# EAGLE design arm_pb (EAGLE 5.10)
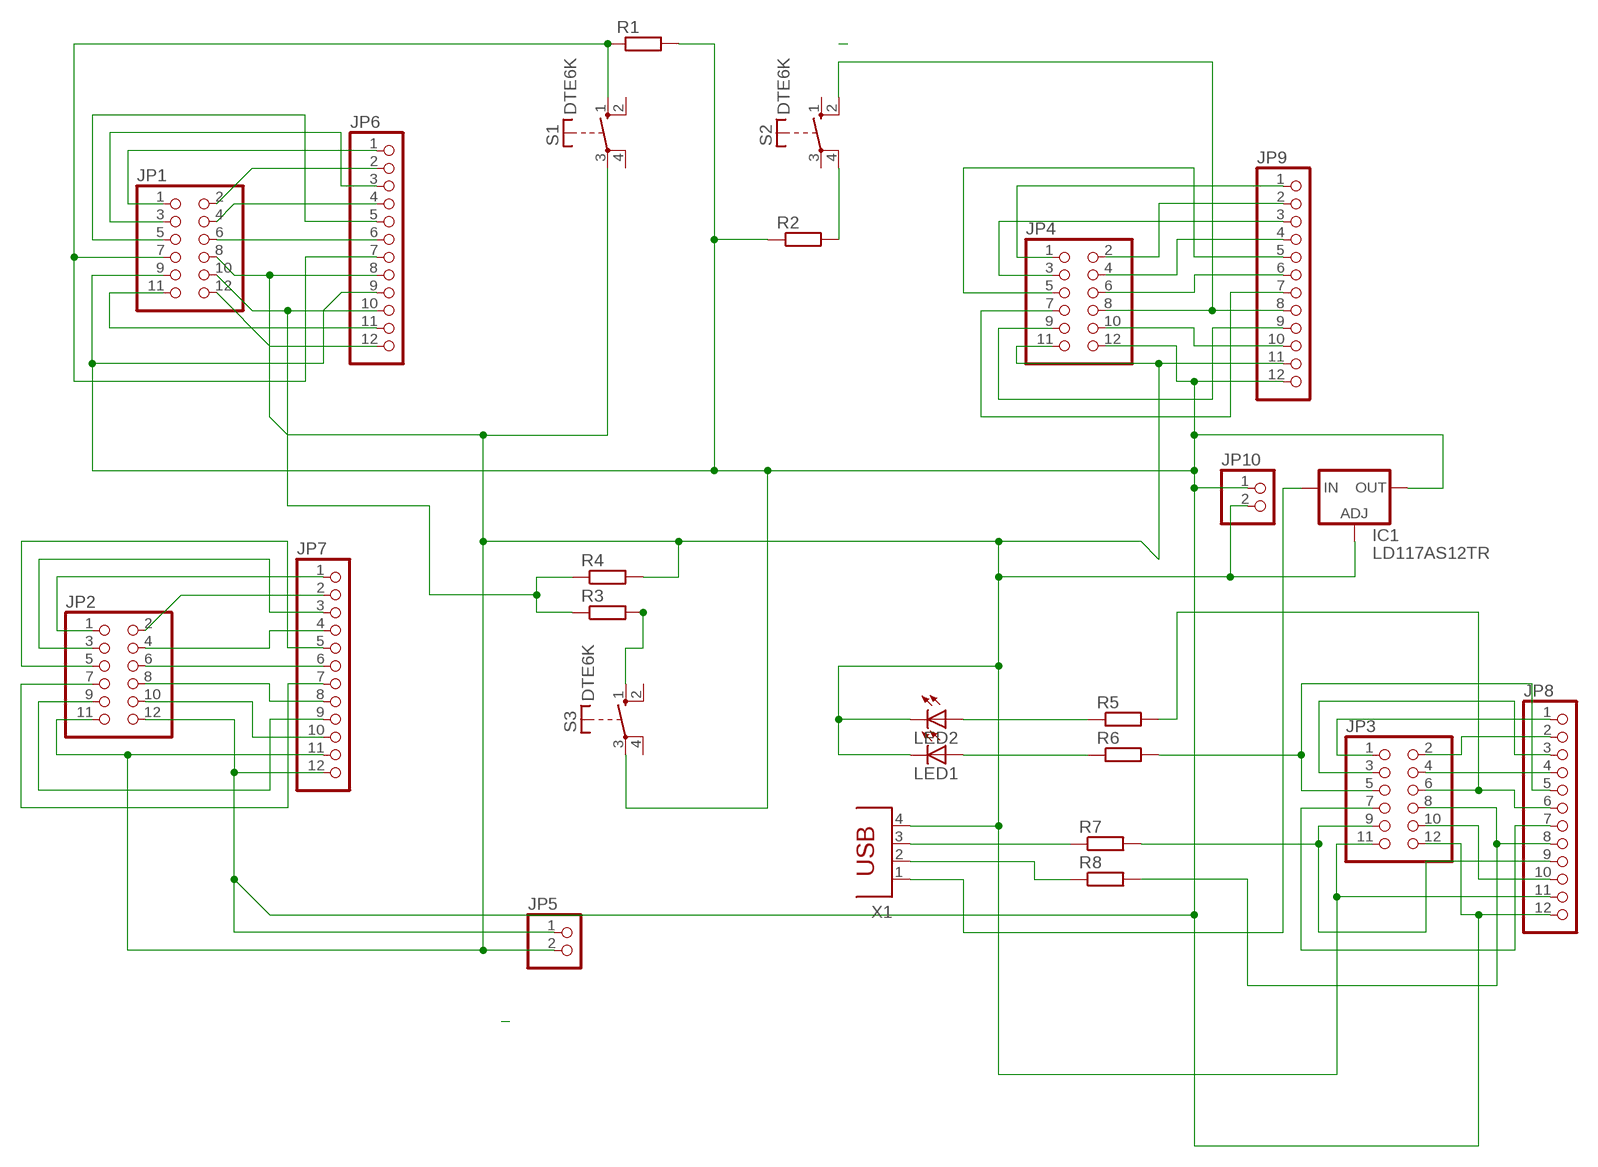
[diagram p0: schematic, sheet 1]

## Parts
IC1  LD117AS12TR  [SOT223]
JP1  PINHD-2X6  [2X06]
JP2  PINHD-2X6  [2X06]
JP3  PINHD-2X6  [2X06]
JP4  PINHD-2X6  [2X06]
JP5  PINHD-1X2  [1X02]
JP6  PINHD-1X12  [1X12]
JP7  PINHD-1X12  [1X12]
JP8  PINHD-1X12  [1X12]
JP9  PINHD-1X12  [1X12]
JP10  PINHD-1X2  [1X02]
LED1  LED3MM  [LED3MM]
LED2  LED3MM  [LED3MM]
R1  R-EU_0204/7  [0204/7]
R2  R-EU_0204/7  [0204/7]
R3  R-EU_0204/7  [0204/7]
R4  R-EU_0204/7  [0204/7]
R5  R-EU_0204/7  [0204/7]
R6  R-EU_0204/7  [0204/7]
R7  R-EU_0204/7  [0204/7]
R8  R-EU_0204/7  [0204/7]
S1  DTE6K  [DTE6K]
S2  DTE6K  [DTE6K]
S3  DTE6K  [DTE6K]
X1  PN61729  [PN61729]

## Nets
N$1: JP1.2 JP6.2
N$3: JP1.4 JP6.4
N$4: JP1.6 JP6.6
N$6: JP1.12 JP6.12
N$7: JP1.10 JP6.10 R3.1 R4.1
N$8: JP1.11 JP6.11
N$10: JP1.7 JP6.7 R1.1 S1.1(S)
N$11: JP1.1 JP6.1
N$12: JP1.3 JP6.3
N$13: JP1.5 JP6.5
N$14: JP3.2 JP8.2
N$15: JP3.4 JP8.4
N$16: JP3.6 JP8.6 R5.2
N$17: JP3.8 JP8.8 R8.2
N$18: JP3.10 JP8.10
N$19: IC1.3(IN) X1.1
N$21: JP3.9 JP8.9 R7.2
N$22: R2.2 S2.4(P)
N$23: R7.1 X1.3
N$24: JP3.1 JP8.1
N$25: JP3.3 JP8.3
N$26: JP3.7 JP8.7
N$27: JP3.5 JP8.5 R6.2
N$28: JP2.2 JP7.2
N$29: JP2.4 JP7.4
N$30: JP2.6 JP7.6
N$31: JP2.8 JP7.8
N$32: JP2.10 JP7.10
N$34: R8.1 X1.2
N$35: JP2.9 JP7.9
N$36: JP2.7 JP7.7
N$37: JP2.1 JP7.1
N$38: JP2.3 JP7.3
N$39: JP2.5 JP7.5
N$41: JP4.2 JP9.2
N$42: JP4.4 JP9.4
N$48: JP4.6 JP9.6
N$50: JP4.8 JP9.8 S2.2(S)
N$53: JP4.10 JP9.10
N$54: LED2.A R5.1
N$55: LED1.A R6.1
N$57: JP4.7 JP9.7
N$58: JP4.1 JP9.1
N$59: JP4.3 JP9.3
N$60: JP4.5 JP9.5
N$61: JP4.9 JP9.9
N$136: R3.2 S3.1(S)
N$179: IC1.1(ADJ) JP1.8 JP2.11 JP3.11 JP4.11 JP5.2 JP6.8 JP7.11 JP8.11 JP9.11 JP10.2 LED1.K(C) LED2.K(C) R4.2 S1.3(P) X1.4
N$183: IC1.4(OUT) JP1.9 JP2.12 JP3.12 JP4.12 JP5.1 JP6.9 JP7.12 JP8.12 JP9.12 JP10.1 R1.2 R2.1 S3.3(P)
Unconnected: S1.2(S) S1.4(P) S2.1(S) S2.3(P) S3.2(S) S3.4(P)

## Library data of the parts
IC1 = v-reg:LD117A?*: Low drop fixed and adjustable positive voltage regulators 1 A Source: http://www.st.com/stonline/products/literature/ds/7194/ld1117axx.pdf
JP1-JP4 = pinhead:PINHD-2X6: PIN HEADER
JP5 JP10 = pinhead:PINHD-1X2: PIN HEADER
JP6-JP9 = pinhead:PINHD-1X12: PIN HEADER
LED1 LED2 = led:LED: LED
R1-R8 = rcl:R-EU_: RESISTOR, European symbol
S1-S3 = switch-misc:DT: ITT SWITCH
X1 = con-berg:PN61729: BERG USB connector

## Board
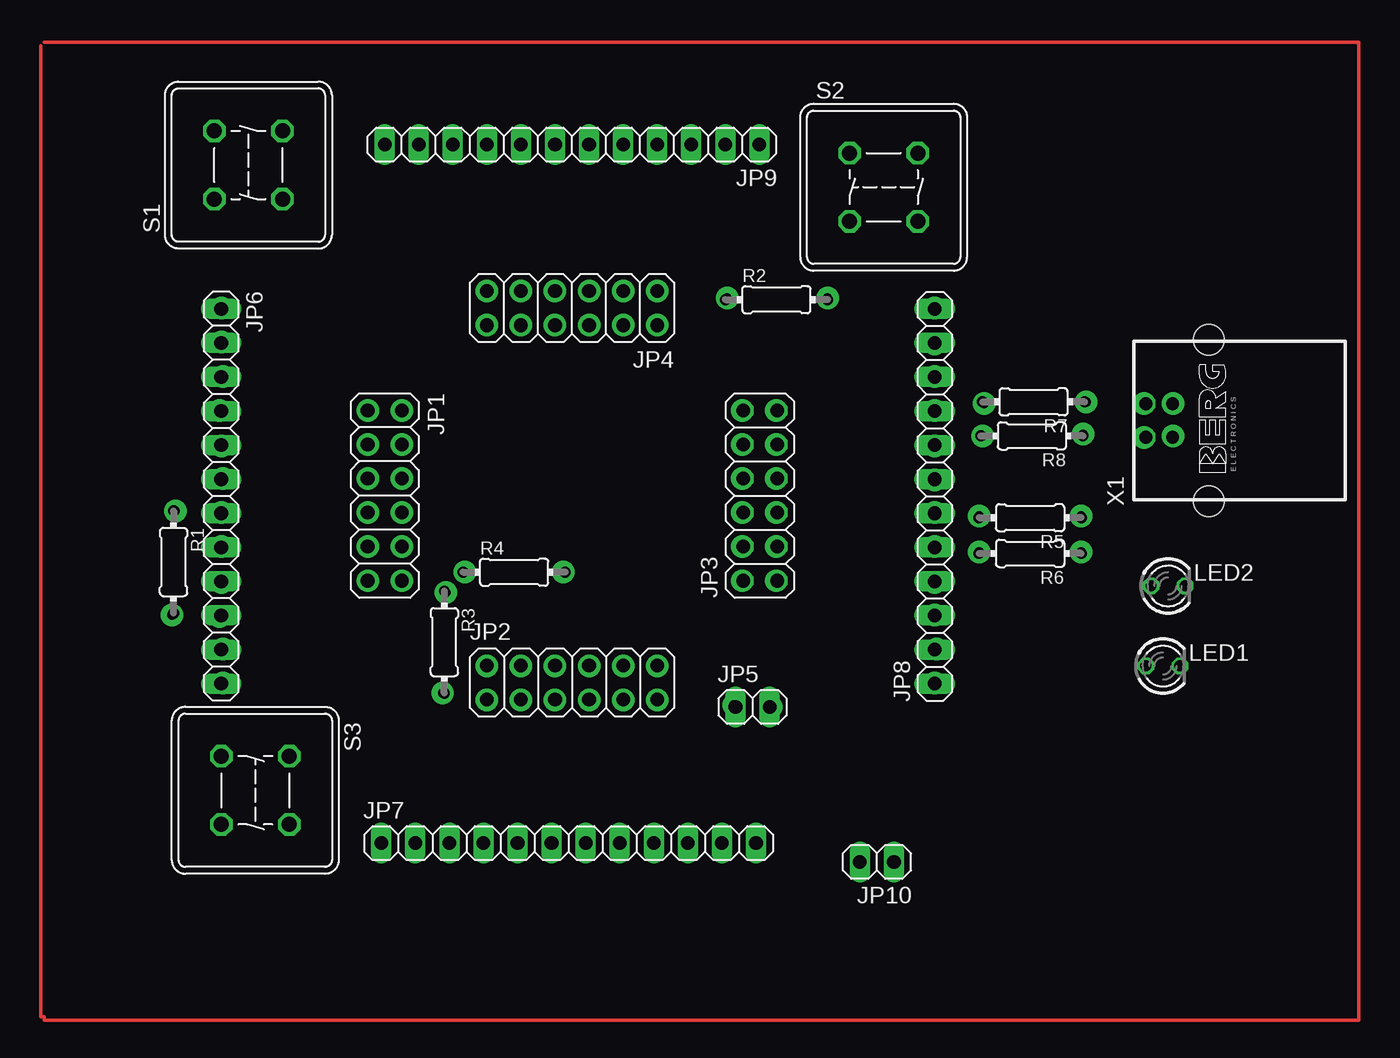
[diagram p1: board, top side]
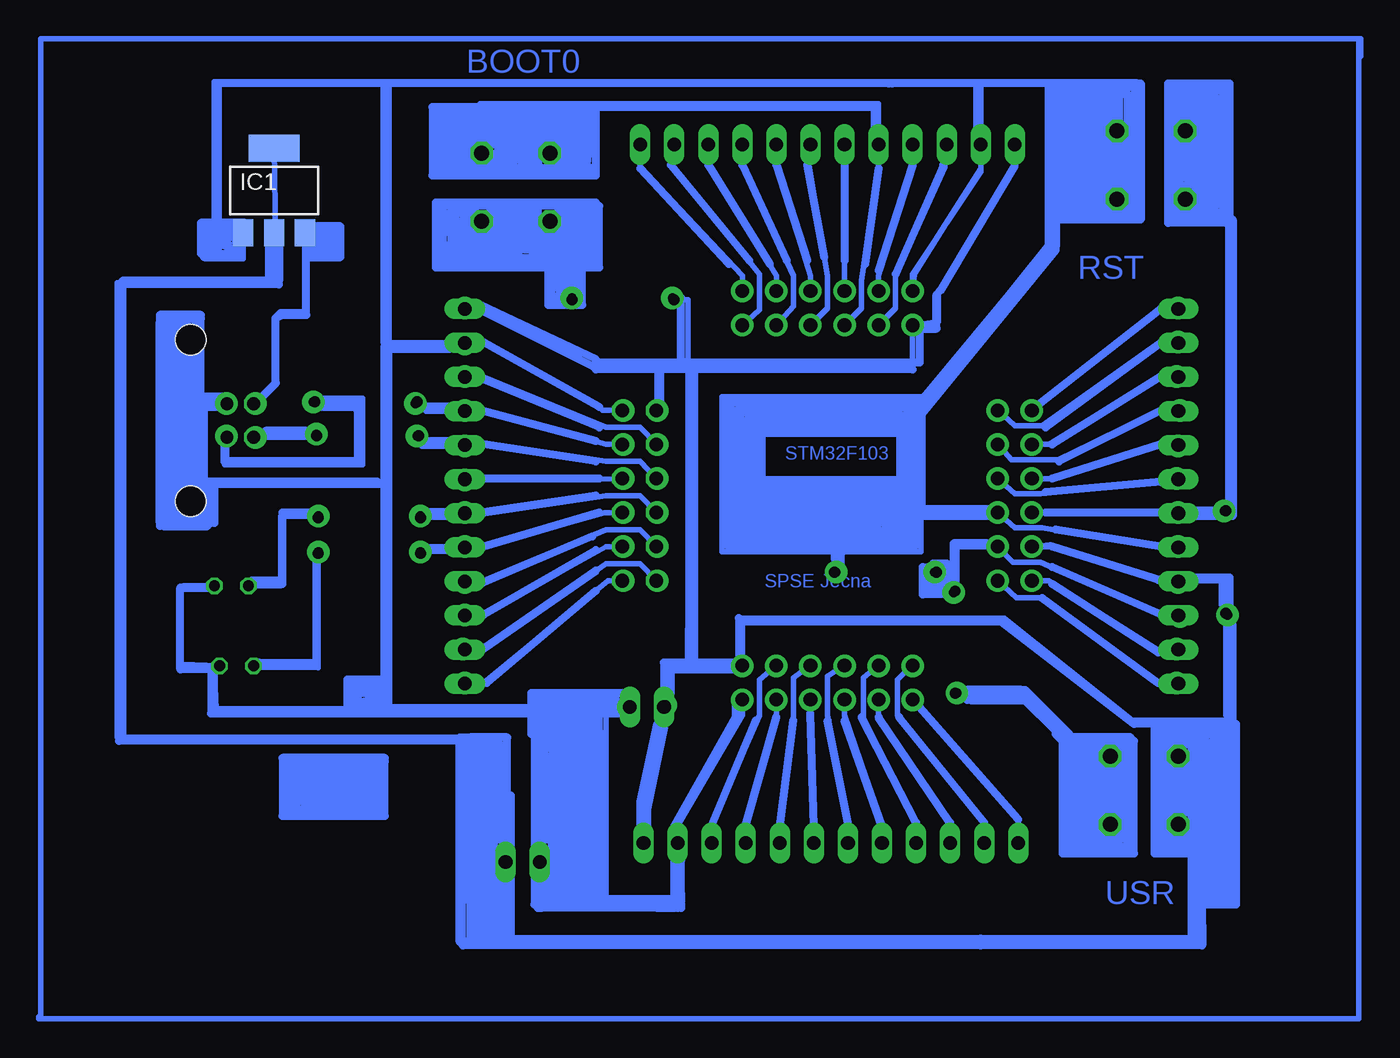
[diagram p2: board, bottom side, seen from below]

No outline drawn. Coordinates in mm, seen from the top.
Copper layers (1*16): Top 0.035mm / dielectric 1.5mm / Bottom 0.035mm
Design rules: minimum track width 0.2mm, minimum drill 0.6mm, track to track 0.2mm, track to pad 0.2mm, pad to pad 0.2mm, via to via 0.2mm, smd to smd 8mil, copper to edge 40mil, drill to drill 2mm, minimum pad ring 0.2mm, minimum via ring 0.3mm, stop-mask expansion 4mil, vias tented up to drill 0mil, thermal gap 10mil

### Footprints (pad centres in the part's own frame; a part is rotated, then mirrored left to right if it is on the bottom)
SOT223 = smd 1.5 x 2: 1 -2.3,-3.15; 2 0,-3.15; 3 2.3,-3.15 | smd 3.8 x 2: 4 0,3.15
2X06 = drill 1.016 octagon: 1 -6.35,-1.27; 2 -6.35,1.27; 3 -3.81,-1.27; 4 -3.81,1.27; 5 -1.27,-1.27; 6 -1.27,1.27; 7 1.27,-1.27; 8 1.27,1.27; 9 3.81,-1.27; 10 3.81,1.27; 11 6.35,-1.27; 12 6.35,1.27
1X02 = drill 1.016 long: 1 -1.27,0; 2 1.27,0
1X12 = drill 1.016 long: 1 -13.97,0; 2 -11.43,0; 3 -8.89,0; 4 -6.35,0; 5 -3.81,0; 6 -1.27,0; 7 1.27,0; 8 3.81,0; 9 6.35,0; 10 8.89,0; 11 11.43,0; 12 13.97,0
LED3MM = drill 0.813 octagon: A -1.27,0; K 1.27,0
0204/7 = drill 0.813 octagon: 1 -3.81,0; 2 3.81,0
DTE6K = drill 1.118 octagon: 1 -2.54,2.54; 2 2.54,2.54; 3 2.54,-2.54; 4 -2.54,-2.54
PN61729 = drill 0.95 octagon: 1 1.25,4.71; 2 -1.25,4.71; 3 -1.25,2.71; 4 1.25,2.71 | hole 2.3: -6.02,0; 6.02,0

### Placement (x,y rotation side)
IC1  67.94,54.48 0 bottom
JP1  12.7,31.75 270 top
JP2  26.67,17.82 0 top
JP3  40.7,31.75 90 top
JP4  26.67,45.72 180 top
JP5  40.13,16 0 top
JP6  0.51,31.7 270 top
JP7  26.42,5.84 0 top
JP8  53.72,31.7 90 top
JP9  26.67,57.91 180 top
JP10  49.4,4.45 180 top
LED1  70.74,19.05 0 top
LED2  71.12,25.02 0 top
R1  -3.05,26.8 270 top
R2  41.91,46.35 0 top
R3  17.14,20.83 270 top
R4  22.35,26.04 0 top
R5  60.83,30.1 180 top
R6  60.83,27.43 180 top
R7  61.09,38.73 180 top
R8  60.96,36.2 180 top
S1  2.54,56.39 90 top
S2  49.91,54.74 0 top
S3  3.05,9.78 270 top
X1  74.17,37.34 90 top

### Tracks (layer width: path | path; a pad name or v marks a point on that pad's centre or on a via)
N$1
  Bottom 0.406: JP1.2 12.7,36.96 10.67,36.96 1.91,43.18 JP6.2
N$2
  Top 0.254: -12.7,65.53 85.34,65.53 85.34,-7.37 -12.7,-7.37 -12.7,-7.11 -12.95,-7.11 -12.95,65.28
N$3
  Bottom 0.406: JP1.4 12.95,34.42 9.53,34.42 1.91,38.1 JP6.4
N$4
  Bottom 0.406: JP1.6 12.7,31.88 10.79,31.88 JP6.6
N$5
  Bottom 0.406: 19.56,39.12 34.54,39.12 34.54,27.56 19.68,27.56 19.68,30.35 21.34,30.35 21.34,33.02 | 21.34,33.15 21.34,36.32 31.5,36.32 31.5,33.02 21.34,33.02 | 21.34,33.02 21.34,33.15 | 21.34,33.15 21.08,33.15 21.08,30.73 19.81,30.73 19.81,37.59 19.81,38.86 34.16,38.86 34.16,27.94 20.07,27.94 20.07,30.1 21.72,30.1 21.72,32.77 31.88,32.77 31.88,36.58 20.95,36.58 20.95,33.4 20.83,33.4 20.83,31.11 20.57,31.11 | 20.32,31.11 20.07,31.11 20.07,38.61 20.32,38.61 | 20.32,38.61 20.32,38.73 | 20.32,38.61 20.32,31.11 | 20.32,31.11 20.57,31.11 | 20.57,31.11 20.57,38.61 33.78,38.61 33.78,28.19 20.45,28.19 20.45,29.84 22.1,29.84 22.1,32.51 32.26,32.51 | 32.26,32.51 32.26,32.38 | 32.26,32.51 32.26,36.83 20.83,36.83 20.83,38.23 33.4,38.23 33.4,28.45 20.7,28.45 20.7,29.59 22.48,29.59 22.48,32.26 32.51,32.26 32.51,37.08 21.21,37.08 21.21,37.34 | 21.21,37.72 21.21,37.85 33.15,37.85 33.15,37.47 33.02,37.47 33.02,28.7 20.95,28.7 20.95,29.21 22.86,29.21 22.86,32 32.77,32 32.77,31.75 32.64,31.75 | 32.64,37.34 32.64,37.72 21.21,37.72 | 21.21,37.72 21.21,37.34 | 21.21,37.34 32.64,37.34 | 32.64,31.75 32.64,37.34 | 32.64,31.75 32.64,28.96 23.11,28.96 | 20.19,28.96 23.11,28.96 | 23.11,28.96 23.11,31.75 32.38,31.75 32.38,29.21 23.5,29.21 23.5,31.24 32.26,31.24 32.26,31.5 23.75,31.5 | 23.37,31.5 23.75,31.5 | 23.75,31.5 23.75,29.46 32.13,29.46 | 32.13,29.46 32.13,29.34 | 32.13,29.46 32.13,30.86 24,30.86 24,29.72 31.75,29.72 31.75,30.61 24.26,30.61 24.26,29.97 31.62,29.97 31.62,30.48 31.37,30.48 31.37,30.23 24.38,30.23
  Bottom 0.61: 9.65,50.04 19.81,37.59
N$6
  Bottom 0.406: JP1.12 12.57,24.13 10.79,24.13 2.03,17.78 JP6.12
  Bottom 0.61: 2.03,17.78 10.67,24.13
N$7
  Bottom 0.406: JP6.10 1.91,22.86 10.79,26.8 12.83,26.8 JP1.10 17.02,27.94 17.02,24.64 R3.1 18.54,24.64 R4.1
N$8
  Bottom 0.406: JP1.11 10.16,25.4 1.91,20.19 JP6.11
N$10  (via drill 0.7 pad 1.68)
  Bottom 0.406: JP1.7 JP6.7 v0.51,30.48 0.51,30.73 -3.05,30.73 | S1.1 -3.17,53.85 -3.17,30.73 -3.05,30.73 | -3.05,30.73 R1.1
N$11
  Bottom 0.406: JP6.1 1.91,45.72 JP1.1
N$12
  Bottom 0.406: JP1.3 10.16,35.56 1.91,40.64 JP6.3
N$13
  Bottom 0.406: JP1.5 10.16,33.02 2.03,35.56 JP6.5
N$14
  Bottom 0.406: JP3.2 40.64,26.67 43.18,26.67 52.45,20.19 JP8.2
N$15
  Bottom 0.406: JP3.4 40.64,29.21 43.18,29.21 52.32,25.4 JP8.4
N$16
  Bottom 0.406: JP3.6 40.64,31.75 43.18,31.75 52.45,30.35 JP8.6 53.9,30.61 56.52,30.61 R5.2
N$17
  Bottom 0.406: JP3.8 40.64,34.29 43.18,34.29 52.32,35.56 JP8.8 53.8,35.43 56.9,35.43 57.15,35.69 R8.2
  Bottom 0.61: 43.94,34.29 52.32,35.56
N$18
  Bottom 0.406: JP3.10 40.64,36.83 43.18,36.83 52.45,40.64 JP8.10
N$19
  Bottom 0.406: X1.1 67.94,40.1 67.94,44.96 67.44,45.47 65.66,45.47 65.64,45.48 IC1.3
N$20
  Bottom 0.61: 5.84,52.58 5.84,61.21 | 5.84,61.21 5.59,61.21 | 5.59,61.21 5.08,61.21 5.08,59.94 9.65,58.93 9.65,60.2 | 9.65,60.71 9.65,61.21 5.84,61.21 | 5.59,61.21 5.33,60.45 9.65,60.2 | 9.65,60.2 9.65,60.71 | 9.65,60.71 6.1,60.71 6.35,52.83 | 3.81,61.72 3.81,52.83 4.32,52.83 | 4.32,52.83 6.35,52.83 | 6.35,52.83 9.91,52.83 9.91,61.72 4.32,61.72 4.32,54.86 | 4.32,54.86 4.32,52.83 | 6.35,52.83 9.4,53.34 9.4,59.69 6.6,59.94 6.6,53.34 7.11,53.34 | 7.11,53.34 8.13,53.34 | 8.13,53.34 8.38,53.34 | 8.89,53.34 9.14,53.34 9.14,59.44 7.11,59.44 7.11,53.34 | 7.11,53.34 7.62,53.59 7.62,59.18 8.38,59.18 8.38,53.34 | 8.38,53.34 8.89,53.34 | 8.89,53.34 8.89,58.93 7.87,58.93 8.13,53.34 | 8.13,53.34 4.57,55.63 4.32,54.86 | 4.32,54.86 5.59,54.86 5.59,57.91 4.57,57.91 4.57,55.88 5.33,55.63 5.33,57.4 5.08,57.4 4.83,55.88
N$21
  Bottom 0.406: JP3.9 43.18,35.56 52.32,38.1 JP8.9 56.59,38.05 R7.2
N$22
  Bottom 0.406: 47.62,52.2 S2.4 45.85,52.2 45.85,46.35 R2.2
N$23
  Bottom 0.406: R7.1 64.64,38.99 61.34,38.99 61.34,34.04 71.63,34.04 71.46,34.21 X1.3
N$24
  Bottom 0.406: JP3.1 43.05,25.4 52.32,17.78 JP8.1
N$25
  Bottom 0.406: JP3.3 43.18,27.94 52.32,22.86 JP8.3
  Bottom 0.61: 43.94,27.69 52.32,22.86
N$26
  Bottom 0.406: JP8.7 JP3.7
N$27
  Bottom 0.406: JP3.5 43.31,30.48 52.32,27.94 JP8.5 53.77,27.94 56.52,27.94 R6.2
  Bottom 0.61: 43.69,30.48 52.32,27.94
N$28
  Bottom 0.406: JP7.2 14.99,7.24 21.46,15.37 21.46,18.03 JP2.2
N$29
  Bottom 0.406: JP7.4 20.07,7.24 24,15.24 24,18.16 JP2.4
N$30
  Bottom 0.406: JP7.6 25.15,7.37 26.67,15.37 26.67,18.29 JP2.6
  Bottom 0.61: 25.15,7.37 26.67,14.99
N$31
  Bottom 0.406: JP7.8 30.23,7.11 30.23,7.24 29.21,15.37 29.21,18.16 JP2.8
  Bottom 0.61: 30.23,7.11 29.21,14.99
N$32
  Bottom 0.406: JP7.10 35.31,7.11 35.31,7.24 31.75,15.37 31.75,18.03 JP2.10
  Bottom 0.61: 35.31,7.11 32,14.99
N$33
  Bottom 0.61: 15.49,58.67 15.49,62.23
N$34
  Bottom 0.406: R8.1 64.88,36.09 X1.2
N$35
  Bottom 0.406: JP7.9 32.77,7.11 30.48,15.37 JP2.9
  Bottom 0.61: 32.77,7.11 30.48,15.24
N$36
  Bottom 0.406: JP7.7 27.69,7.11 27.69,7.24 27.94,15.37 27.94,15.49 JP2.7
  Bottom 0.61: 27.69,7.11 27.94,15.49
N$37
  Bottom 0.406: JP7.1 12.45,7.62 JP2.1
  Bottom 0.61: 12.45,7.62 19.81,16
N$38
  Bottom 0.406: JP7.3 17.53,7.24 22.86,15.37 JP2.3
N$39
  Bottom 0.406: JP7.5 22.61,7.11 22.61,7.24 25.4,15.37 JP2.5
  Bottom 0.61: 22.61,7.11 25.4,14.99
N$40  (via drill 0.7 pad 1.68)
  other vias: 20.32,44.45
N$41
  Bottom 0.406: JP4.2 31.75,45.59 31.75,48.26 38.23,56.39 JP9.2
N$42
  Bottom 0.406: JP4.4 29.21,45.85 29.21,48.13 33.02,56.39 JP9.4
  Bottom 0.61: 33.02,56.39 29.72,49.28
N$43  (via drill 0.7 pad 1.68)
  other vias: 30.48,44.45
N$44  (via drill 0.7 pad 1.68)
  other vias: 25.4,44.45
N$45  (via drill 0.7 pad 1.68)
  other vias: 33.02,44.45
N$46  (via drill 0.7 pad 1.68)
  other vias: 27.94,44.45
N$47  (via drill 0.7 pad 1.68)
  other vias: 22.86,44.45
N$48
  Bottom 0.406: JP4.6 26.67,45.72 26.67,48.13 28.07,56.39 JP9.6
N$49  (via drill 0.7 pad 1.68)
  other vias: 20.32,46.99
N$50
  Bottom 0.406: JP4.8 24.13,45.72 24.13,47.75 22.86,56.26 JP9.8 22.86,60.96 52.58,60.96 52.58,60.58 52.45,60.58 S2.2
N$51  (via drill 0.7 pad 1.68)
  other vias: 22.86,46.99
N$52  (via drill 0.7 pad 1.68)
  other vias: 25.4,46.99
N$53
  Bottom 0.406: JP4.10 21.59,45.72 21.59,48.13 17.91,56.26 JP9.10
N$54
  Bottom 0.406: R5.1 64.77,30.23 67.31,30.23 67.44,30.23 67.44,25.02 LED2.A
  Bottom 0.61: 67.31,25.15 67.31,30.23
N$55
  Bottom 0.406: LED1.A 64.64,18.92 R6.1
N$56  (via drill 0.7 pad 1.68)
  other vias: 39.37,38.1
N$57
  Bottom 0.406: JP4.7 25.4,49.28 | 25.4,56.64 JP9.7
  Bottom 0.61: 25.4,56.64 25.4,49.28
N$58
  Bottom 0.406: JP4.1 33.02,48.13 40.64,56.26 JP9.1
N$59
  Bottom 0.406: JP4.3 30.48,48.13 35.56,56.39 JP9.3
  Bottom 0.61: 35.56,56.39 30.99,49.02
N$60
  Bottom 0.406: JP4.5 27.94,48.13 30.48,56.26 30.48,56.39 JP9.5
  Bottom 0.61: 30.48,56.39 28.19,49.28
N$61
  Bottom 0.406: JP4.9 22.86,48.13 20.32,56.26 20.32,56.39 JP9.9
  Bottom 0.61: 20.32,56.39 22.86,48.51
N$62  (via drill 0.7 pad 1.68)
  other vias: 20.32,19.05
N$63  (via drill 0.7 pad 1.68)
  other vias: 22.86,19.05
N$64  (via drill 0.7 pad 1.68)
  other vias: 25.4,19.05
N$65  (via drill 0.7 pad 1.68)
  other vias: 27.94,19.05
N$66  (via drill 0.7 pad 1.68)
  other vias: 30.48,19.05
N$67  (via drill 0.7 pad 1.68)
  other vias: 33.02,19.05
N$68  (via drill 0.7 pad 1.68)
  other vias: 20.32,16.51
N$69  (via drill 0.7 pad 1.68)
  other vias: 22.86,16.51
N$70  (via drill 0.7 pad 1.68)
  other vias: 25.4,16.51
N$71  (via drill 0.7 pad 1.68)
  other vias: 27.94,16.51
N$72  (via drill 0.7 pad 1.68)
  other vias: 30.48,16.51
N$73  (via drill 0.7 pad 1.68)
  other vias: 33.02,16.51
N$74  (via drill 0.7 pad 1.68)
  other vias: 27.94,46.99
N$75  (via drill 0.7 pad 1.68)
  other vias: 30.48,46.99
N$76  (via drill 0.7 pad 1.68)
  other vias: 33.02,46.99
N$77  (via drill 0.7 pad 1.68)
  other vias: 39.37,35.56
N$78  (via drill 0.7 pad 1.68)
  other vias: 39.37,33.02
N$80  (via drill 0.7 pad 1.68)
  other vias: 39.37,30.48
N$81  (via drill 0.7 pad 1.68)
  other vias: 39.37,27.94
N$82  (via drill 0.7 pad 1.68)
  other vias: 39.37,25.4
N$83  (via drill 0.7 pad 1.68)
  other vias: 41.91,38.1
N$84  (via drill 0.7 pad 1.68)
  other vias: 41.91,35.56
N$85  (via drill 0.7 pad 1.68)
  other vias: 41.91,33.02
N$86  (via drill 0.7 pad 1.68)
  other vias: 41.91,30.48
N$87  (via drill 0.7 pad 1.68)
  other vias: 41.91,27.94
N$88  (via drill 0.7 pad 1.68)
  other vias: 41.91,25.4
N$89  (via drill 0.7 pad 1.68)
  other vias: 57.02,27.56
N$90  (via drill 0.7 pad 1.68)
  other vias: 57.02,30.23
N$91  (via drill 0.7 pad 1.68)
  other vias: 57.28,36.2
N$92  (via drill 0.7 pad 1.68)
  other vias: 57.4,38.61
N$93  (via drill 0.7 pad 1.68)
  other vias: 53.72,27.94
N$94  (via drill 0.7 pad 1.68)
  other vias: 53.72,25.27
N$95  (via drill 0.7 pad 1.68)
  other vias: 53.72,22.86
N$96  (via drill 0.7 pad 1.68)
  other vias: 53.72,30.48
N$97  (via drill 0.7 pad 1.68)
  other vias: 53.72,32.89
N$98  (via drill 0.7 pad 1.68)
  other vias: 53.72,35.43
N$99  (via drill 0.7 pad 1.68)
  other vias: 53.72,38.1
N$100  (via drill 0.7 pad 1.68)
  other vias: 53.72,40.64
N$101  (via drill 0.7 pad 1.68)
  other vias: 53.72,43.05
N$102  (via drill 0.7 pad 1.68)
  other vias: 53.72,45.72
N$103  (via drill 0.7 pad 1.68)
  other vias: 45.72,46.48
N$104  (via drill 0.7 pad 1.68)
  other vias: 38.23,46.48
N$105  (via drill 0.7 pad 1.68)
  other vias: 65.02,38.73
N$106  (via drill 0.7 pad 1.68)
  other vias: 64.64,30.23
N$107  (via drill 0.7 pad 1.68)
  other vias: 64.64,27.56
N$108  (via drill 0.7 pad 1.68)
  other vias: 53.85,20.32
N$109  (via drill 0.7 pad 1.68)
  other vias: 53.72,17.78
N$110  (via drill 0.7 pad 1.68)
  other vias: 38.73,16.13
N$111  (via drill 0.7 pad 1.68)
  other vias: 0.64,17.78
N$112  (via drill 0.7 pad 1.68)
  other vias: 0.64,20.32
N$113  (via drill 0.7 pad 1.68)
  other vias: 0.38,22.73
N$114  (via drill 0.7 pad 1.68)
  other vias: 0.51,25.27
N$115  (via drill 0.7 pad 1.68)
  other vias: 0.51,27.94
N$116  (via drill 0.7 pad 1.68)
  other vias: 0.51,45.72
N$117  (via drill 0.7 pad 1.68)
  other vias: 0.51,43.18
N$118  (via drill 0.7 pad 1.68)
  other vias: 0.64,40.64
N$119  (via drill 0.7 pad 1.68)
  other vias: 0.38,38.1
N$120  (via drill 0.7 pad 1.68)
  other vias: 0.51,35.43
N$121  (via drill 0.7 pad 1.68)
  other vias: 0.64,33.02
N$122  (via drill 0.7 pad 1.68)
  other vias: -2.92,30.61
N$123  (via drill 0.7 pad 1.68)
  other vias: 17.27,24.51
N$124  (via drill 0.7 pad 1.68)
  other vias: 18.67,26.04
N$125  (via drill 0.7 pad 1.68)
  other vias: 26.04,26.04
N$126  (via drill 0.7 pad 1.68)
  other vias: 64.77,36.32
N$127  (via drill 0.7 pad 1.68)
  other vias: 69.34,36.07
N$128  (via drill 0.7 pad 1.68)
  other vias: 69.34,38.61
N$129  (via drill 0.7 pad 1.68)
  other vias: 71.5,36.2
N$130  (via drill 0.7 pad 1.68)
  other vias: 74.17,31.37
N$131  (via drill 0.7 pad 1.68)
  other vias: 74.17,43.31
N$132
  Bottom 0.406: -12.95,65.79 -13.08,65.79 -13.08,64.52 | -12.95,65.79 -12.95,-7.24 85.47,-7.24 85.47,-7.11 85.34,-7.11 85.34,65.79 -12.95,65.79
N$133
  Bottom 0.61: -3.05,52.07 1.27,52.07 1.27,62.48 -3.3,62.48 -3.3,52.32 0.76,52.32 0.76,58.17 | 0.76,58.17 0.76,61.98 -2.79,61.98 -2.79,52.83 0.51,52.83 -1.02,53.34 -1.27,53.34 | -1.78,53.34 -2.29,53.34 -2.29,61.47 0.25,61.47 0.25,59.69 -2.03,59.69 -1.78,60.96 -0.25,60.96 -0.25,60.2 -1.78,60.2 -1.78,60.45 -0.51,60.45 -1.78,59.18 -1.78,53.34 | -1.78,53.34 -1.27,53.34 | -1.27,53.34 -1.27,59.44 -0.76,59.44 -0.76,53.34 | -0.51,58.17 0.76,58.17 | 0.76,58.17 0.51,54.86 -0.25,54.86 -0.25,57.91 0.25,57.66 0.25,55.37
N$134
  Bottom 0.61: -3.56,52.32 -3.56,32.26 -3.56,32 -3.56,30.23
N$135
  Bottom 0.61: 38.1,4.57 38.1,2.03 37.59,2.03 | 37.59,2.03 37.59,4.57 | 37.59,1.52 43.43,1.52 43.43,3.3 | 43.43,3.3 43.43,13.97 43.69,13.97 | 43.69,13.97 48.51,13.97 48.51,1.27 39.37,1.27 39.37,1.02 | 39.37,1.02 38.1,1.02 | 37.85,1.02 37.85,1.27 37.59,1.27 | 37.59,1.27 37.59,1.52 | 37.59,1.27 37.59,1.02 38.1,1.02 | 39.37,1.02 48.01,1.02 | 48.26,1.02 48.01,1.02 | 48.01,1.02 48.01,3.3 43.94,3.3 | 43.43,3.3 43.94,3.3 | 43.94,3.3 43.94,1.78 47.5,1.78 47.5,2.79 44.2,2.79 44.2,2.29 46.99,2.29 | 46.99,2.29 46.99,2.03 | 46.99,2.29 46.99,3.05 | 46.99,6.1 46.99,6.35 47.24,6.35 47.24,3.05 46.99,3.05 | 46.99,3.05 46.99,6.1 | 46.99,6.1 48.26,6.1 48.26,13.46 43.94,13.46 43.94,3.56 46.48,3.56 46.48,6.35 47.75,6.35 47.75,12.95 44.45,12.95 44.45,3.81 45.97,3.81 45.97,6.6 47.24,6.6 47.24,12.45 44.96,12.45 44.96,4.32 45.47,4.32 | 45.47,4.32 45.47,4.06 | 45.47,4.32 45.47,6.86 46.74,6.86 46.74,11.94 45.21,11.94 45.21,7.37 46.23,7.37 46.23,7.62 46.48,7.62 46.48,11.68 45.47,11.68 45.47,7.87 45.97,7.87 | 45.97,7.87 45.97,7.62 | 45.97,7.87 45.97,11.43 | 37.59,2.03 37.59,1.52 | 38.1,1.02 38.1,1.27 | 43.69,13.97 43.69,15.75 44.2,15.75 44.2,14.22
N$136  (via drill 0.7 pad 1.68)
  Bottom 0.406: R3.2 v17.02,17.02 16.51,17.02 12.19,17.02 12.19,17.14 8.26,13.21 8.26,12.19 8.13,12.32 S3.1
  Bottom 0.61: 4.06,13.72 8.64,13.72 | 8.64,13.72 9.14,13.72 9.14,13.46 | 9.14,13.46 9.14,5.08 3.81,5.08 3.81,13.46 8.64,13.46 8.64,5.59 4.32,5.59 4.32,12.95 8.13,12.95 | 8.13,12.95 8.13,13.21 | 8.13,12.95 8.13,5.84 5.33,5.84 5.33,6.1 | 5.33,6.1 5.08,6.1 | 5.08,6.1 4.83,6.1 4.83,8.13 | 4.83,12.7 4.83,8.13 | 4.83,8.13 7.87,8.13 7.87,12.45 6.35,12.45 6.35,6.35 5.08,6.35 5.08,6.1 | 5.33,6.1 7.62,6.1 7.62,12.19 6.6,12.19 6.6,11.94 6.86,11.94 6.86,6.35 7.37,6.35 7.37,11.68 5.08,11.68 5.08,8.64 5.84,8.64 5.84,11.18 5.59,11.18 5.59,9.14 | 9.14,13.46 9.65,13.97 9.65,14.22 11.94,16.51 | 12.19,16.76 12.45,16.76 12.7,17.02 16.51,17.02 16,16.51 11.94,16.51 | 11.94,16.51 12.19,16.76 | 12.19,16.76 12.19,17.27 16.26,17.27 16.26,16.51 15.49,17.27 11.94,17.27 8.64,13.97 8.64,13.72
N$137
  Bottom 0.61: 33.53,16.26 33.53,15.24 38.1,7.11
N$138
  Bottom 0.61: 39.37,14.73 40.64,8.89 40.64,7.11
N$139
  Bottom 0.61: 19.81,44.2 19.81,41.66 43.69,41.66
N$140
  Bottom 0.61: 59.18,15.75 72.39,15.75 72.39,18.54 72.64,18.8 72.64,15.49 59.44,15.49 | 41.91,15.49 59.44,15.49 | 59.44,15.49 59.44,23.88
N$141
  Bottom 0.61: 69.09,19.05 64.77,19.05
N$142
  Bottom 0.61: 53.85,13.46 79.5,13.46
N$143
  Bottom 0.61: -3.56,14.99 -3.56,22.1
N$144
  Bottom 0.61: -0.76,25.65 -3.3,25.65 -3.3,23.62
N$145
  Bottom 0.61: 14.48,30.73 19.3,30.73
N$146
  Bottom 0.61: 14.73,30.23 19.56,30.23
N$147
  Bottom 0.61: 17.53,24.89 18.29,24.89 18.29,26.16
N$149
  Bottom 0.61: 25.91,27.43 25.91,26.42 25.65,26.42 25.65,27.43
N$150
  Bottom 0.61: -2.79,30.23 0,30.23
N$151
  Bottom 0.61: 1.52,30.48 10.41,30.48
N$152
  Bottom 0.61: 1.78,27.94 9.65,29.21
N$153
  Bottom 0.61: 1.78,22.86 9.91,26.42
N$154
  Bottom 0.61: 2.03,20.07 9.91,25.15
N$155
  Bottom 0.61: 1.78,32.77 10.41,32
N$156
  Bottom 0.61: 1.78,35.56 9.91,33.02
N$157
  Bottom 0.61: 1.78,38.1 9.4,34.29
N$158
  Bottom 0.61: 1.78,40.64 9.91,35.56
N$159
  Bottom 0.61: 1.78,43.18 10.41,36.83
N$160
  Bottom 0.61: 1.78,45.72 11.18,38.35
N$161
  Bottom 0.61: 19.56,44.2 18.54,44.2 18.54,46.74
N$164
  Bottom 0.61: 39.12,38.35 39.12,41.4
N$165
  Bottom 0.61: 37.59,41.91 37.59,46.48
N$166
  Bottom 0.61: 43.94,41.91 52.58,45.97
N$167
  Bottom 0.61: 59.69,18.03 59.69,42.93 | 59.69,18.03 59.69,16 | 59.69,18.03 62.48,18.03 62.48,16 62.23,16 | 62.23,16 60.2,16 60.2,17.53 61.98,17.53 62.23,16 | 62.23,16 60.71,16.26 60.71,17.02 61.72,17.02 61.72,16.26 60.96,16.51
N$168
  Bottom 0.61: 59.44,42.67 59.44,62.23
N$169
  Bottom 0.61: 23.11,59.18 23.11,60.71 56.13,60.71 56.13,55.63 43.94,55.63 43.94,60.45 55.88,60.45 55.88,55.88 44.96,55.88 | 44.96,55.88 44.7,55.88 | 44.7,55.88 44.7,60.2 44.2,60.2 44.7,55.88 | 44.7,55.88 44.2,56.13 45.47,56.13 | 45.47,56.13 53.09,56.13 | 53.09,56.13 54.1,56.13 | 54.1,56.13 55.63,56.13 55.63,59.69 | 55.63,59.69 55.63,60.2 44.96,59.94 44.96,55.88 | 44.96,55.88 45.47,56.13 | 45.47,56.13 45.47,59.69 55.12,59.69 | 55.63,59.69 55.12,59.69 | 55.12,59.69 55.12,56.39 54.61,56.39 54.61,59.18 45.97,59.18 45.97,58.67 54.36,58.67 54.36,58.17 53.85,58.17 | 53.85,58.17 53.34,58.17 | 53.34,58.17 49.02,58.17 | 48.51,58.17 45.97,58.17 45.97,56.64 46.23,56.64 | 46.23,56.64 46.74,56.64 46.48,57.91 46.23,56.64 | 46.23,56.64 45.97,58.42 48.26,58.42 48.26,56.39 | 49.02,56.39 49.02,58.17 | 49.02,58.17 48.51,58.17 | 48.51,58.17 48.51,56.39 | 53.09,56.13 53.34,58.17 | 53.34,58.17 53.59,57.91 53.85,56.64 53.59,56.64 53.85,58.17 | 53.85,58.17 54.1,57.91 54.1,56.13
N$170
  Bottom 0.61: 49.53,56.64 49.53,57.91 52.07,57.91 51.82,56.64 50.04,56.64 50.04,57.4 51.31,57.4 51.31,56.9 50.29,57.15
N$171
  Bottom 0.61: 43.94,53.59 55.88,53.59 55.88,53.34 | 55.88,53.34 55.88,48.77 47.5,48.77 47.5,45.97 44.96,45.97 44.96,48.77 43.69,48.77 43.69,53.34 55.37,53.34 | 55.88,53.34 55.37,53.34 | 55.37,53.34 55.37,49.28 54.86,49.28 | 54.86,49.28 53.59,49.28 | 53.34,49.28 52.83,49.28 | 52.83,49.28 51.56,49.28 | 51.56,49.28 44.45,49.28 | 44.45,49.28 43.94,49.28 44.2,53.09 | 44.45,49.28 44.45,53.09 46.74,53.09 46.74,49.53 44.96,49.53 44.96,52.58 45.21,52.58 | 45.72,52.58 46.48,52.58 46.48,49.78 45.47,49.78 | 45.47,49.78 45.97,52.07 45.97,47.24 | 45.97,47.24 46.48,47.24 | 46.48,47.24 46.99,47.24 46.99,49.02 46.48,49.02 | 46.48,49.02 44.7,49.02 45.21,52.58 | 45.21,52.58 45.72,52.58 | 45.72,52.58 45.47,49.78 | 45.47,49.78 45.47,47.24 45.97,47.24 | 46.48,47.24 46.48,49.02 | 46.48,49.02 46.74,46.23 47.24,46.23 47.24,51.31 49.28,51.31 | 49.28,51.31 54.86,51.31 54.86,52.83 52.83,52.83 53.34,52.58 53.34,49.28 | 53.34,49.28 53.59,49.28 | 53.59,49.28 53.85,52.32 53.85,49.53 54.36,49.78 54.36,52.32 54.61,52.58 54.86,49.28 | 54.86,49.28 48.01,49.53 47.75,49.78 47.75,51.05 53.09,51.05 52.83,49.28 | 52.83,49.28 48.77,49.53 48.26,50.04 48.26,53.09 51.82,53.09 51.56,49.28 | 51.56,49.28 52.83,50.55 48.77,50.55 48.77,50.04 52.32,50.29 52.58,49.78 49.53,50.04 48.77,51.82 48.77,52.58 51.31,52.83 51.31,51.56 49.53,51.56 49.53,52.32 49.28,52.07 49.28,51.31 | 49.28,51.31 50.29,52.07 50.04,52.32 51.05,52.58 51.05,51.82 50.55,52.07
N$172
  Bottom 0.61: 54.86,42.67 59.18,42.67
N$173
  Bottom 0.61: 54.86,38.35 56.64,38.35
N$174
  Bottom 0.61: 54.86,35.81 56.64,35.81
N$175
  Bottom 0.61: 64.77,38.35 61.47,38.35 61.47,38.61 64.01,38.86
N$176
  Bottom 0.61: 65.53,36.58 68.58,36.58
N$177
  Bottom 0.61: 61.72,38.1 61.72,34.29 71.63,34.29 71.63,35.56
N$178
  Bottom 0.61: 68.83,39.12 67.82,40.13 67.82,44.96 67.31,45.21 65.53,45.21 65.53,49.53 | 65.53,50.29 65.53,49.53 | 65.53,49.53 62.99,49.53 62.99,51.82 65.53,51.82 65.28,49.78 63.25,49.78 63.5,51.31 65.02,51.31 65.02,50.29 63.75,50.29 63.75,50.8 64.77,50.8
N$179  (via drill 0.7 pad 1.68)
  Bottom 0.406: JP3.11 43.43,38.1 52.32,43.18 JP8.11 59.31,43.18 | JP4.11 20.32,48.13 15.24,56.13 | JP9.11 15.24,56.13 | JP7.11 37.85,7.11 33.02,15.37 | JP1.8 12.7,29.34 10.67,29.34 2.03,27.94 JP6.8 0.56,27.94 1.27,27.94 | JP4.11 20.19,48.26 15.24,56.13 | 59.31,16 v41.53,16 JP5.2 43.18,15.99 | 59.31,32.51 59.31,16 | 59.31,43.18 59.31,32.51 | 59.31,16 43.18,15.99 | 59.31,32.51 59.31,15.87 | 59.31,16 59.31,15.87 | 33.02,15.37 JP2.11 33.15,16.64 33.15,16.51 | 33.02,15.37 37.97,6.99 JP7.11 | JP7.11 37.85,1.78 43.18,1.78 43.18,4.45 | 43.18,15.99 43.18,4.45 | X1.4 71.48,38.61 v71.5,38.61 72.77,38.61 73.41,37.97 73.41,32.77 73.03,32.64 72.01,32.51 59.31,32.51 | LED2.K 74.68,25.02 74.93,24.77 74.93,19.3 74.8,19.18 LED1.K 72.39,19.05 72.26,15.88 72.01,15.87 59.31,15.87 | S1.3 4.83,59.18 4.83,62.48 4.95,62.61 15.37,62.61 15.24,62.48 | 15.24,62.48 JP9.11 | JP4.11 20.32,48.26 15.24,55.88 JP9.11 | 10.16,62.48 15.24,62.48 | 10.16,62.48 10.16,62.23 10.16,50.55 19.56,38.86 | 19.56,30.61 19.56,30.35 JP1.8 | 19.56,30.61 19.56,38.61 19.56,38.86 | JP1.8 26.29,30.35 R4.2 26.42,30.35 19.56,30.61 | 19.56,38.86 19.56,39.12 10.03,50.55 10.16,62.48 | 15.24,62.48 21.84,62.48 | 22.1,62.48 59.82,62.48 | 59.82,62.48 60.07,62.48 60.96,62.61 72.39,62.61 72.39,49.4 70.23,49.4 IC1.1 | 59.82,62.48 59.82,43.18 59.31,43.18 | 43.18,4.45 JP10.2
  Bottom 0.61: 70.1,52.07 73.41,52.07 73.41,49.78 70.61,49.78 70.87,51.82 73.15,51.82 73.15,51.31 | 73.15,51.31 73.15,49.53 72.14,49.53 | 3.3,62.48 3.3,52.32 9.65,52.32 9.65,50.29 10.16,49.78 10.16,62.23 3.56,62.23 3.56,62.48 21.84,62.48 22.1,62.48 72.14,62.48 72.14,50.55 | 19.56,38.61 10.16,50.04 | 72.14,50.55 72.14,49.53 | 72.14,49.53 70.61,49.53 | 70.61,49.53 70.36,49.53 70.36,50.8 | 70.61,49.53 70.87,51.56 73.15,51.31 | 73.15,51.31 72.64,50.04 72.9,51.05 70.61,51.05 70.87,50.04 72.14,50.55 | 72.14,50.55 71.37,50.55 | 43.69,38.35 52.32,43.18
N$180
  Bottom 0.61: 60.2,32.77 73.15,32.77 73.15,38.35 72.14,38.35
N$181
  Bottom 0.61: 68.33,50.55 68.33,47.75
N$182
  Bottom 0.61: 67.56,50.8 67.56,47.75 79.25,47.75
N$183  (via drill 0.7 pad 1.68)
  Bottom 0.406: JP9.12 12.7,56.39 12.7,56.26 18.41,46.86 18.41,44.7 JP4.12 20.32,41.53 37.08,41.53 | JP3.12 39.37,39.37 39.37,41.53 | JP8.12 52.32,45.72 43.18,41.53 39.37,41.53 | 37.08,41.53 39.37,41.53 | JP6.9 2.03,25.35 2.03,25.4 | 2.03,25.4 9.91,27.94 JP1.9 10.03,28.07 2.03,25.4 | 2.03,25.4 1.78,25.4 -2.79,25.4 -3.17,25.4 v-3.17,22.86 -3.17,14.99 | -1.4,14.99 -3.17,14.99 | -1.4,14.99 3.94,14.99 13.46,22.61 33.02,22.61 JP2.12 37.09,19.15 | 37.09,19.15 38.86,19.18 38.86,17.02 JP5.1 38.86,14.48 38.86,14.35 40.39,8.38 JP7.12 | 37.08,41.53 37.08,24.64 37.09,19.15 | -3.17,14.99 -3.3,14.99 -3.3,15.37 -3.05,15.37 R1.2 | R2.1 37.08,46.35 37.08,41.53 | S3.3 0.25,6.99 -1.27,6.99 | -1.27,6.99 -1.4,7.11 -1.4,14.99 | IC1.4 67.82,51.05 67.94,47.62 79.63,47.62 79.63,13.72 79.25,13.72 54.1,13.72 | 53.85,13.72 53.72,13.72 53.8,4.45 | 53.8,4.45 53.85,-1.78 -1.4,-1.65 -1.27,6.99 | 53.8,4.45 JP10.1
  Bottom 0.61: 67.56,47.5 79.25,47.5 | 79.25,47.5 79.5,47.5 | 53.34,13.72 53.85,13.72 54.1,13.72 54.1,-1.52 53.85,-1.52 | 53.34,4.57 53.34,-1.52 | 53.34,-1.52 53.85,-1.52 | 53.34,13.72 53.34,9.4 | 53.34,4.83 53.34,4.57 | 53.34,4.57 53.09,4.57 53.09,4.83 53.34,4.83 | 53.34,4.83 53.34,9.4 | 53.34,9.4 50.29,9.4 50.29,-1.27 | 50.29,-1.27 53.09,-1.27 53.09,-1.52 52.83,-1.52 52.83,9.14 50.55,9.14 | 50.55,9.14 50.55,8.64 50.8,8.64 50.8,6.1 52.32,6.1 | 52.32,6.1 52.32,8.89 51.05,8.89 51.05,6.6 51.82,6.6 51.82,8.38 51.56,8.38 | 51.31,8.38 51.56,8.38 | 51.56,8.38 51.56,-0.76 | 51.56,-0.76 51.82,-0.76 | 51.82,-0.76 52.32,-0.76 | 52.32,-0.76 52.32,-1.02 | 52.32,-0.76 52.32,5.84 | 52.32,5.84 52.32,6.1 | 52.32,5.84 51.82,5.84 51.82,-0.76 | 51.56,-0.76 51.05,-0.76 | 51.05,-0.76 50.8,-0.76 50.8,3.05 51.05,3.05 | 51.31,3.05 51.05,3.05 | 51.05,3.05 51.05,-0.76 | 52.32,-0.76 52.58,-0.76 52.58,0.51 | 50.29,-1.27 15.24,-1.27 | 15.24,-1.78 53.85,-1.78 53.85,-1.52 | 53.34,-1.52 -1.02,-1.52 -1.02,-1.02 -1.27,-1.02 -1.27,-1.78 15.24,-1.78 | 15.24,-1.78 15.24,-1.27 | 15.24,-1.27 -0.76,-1.27 -0.76,-1.02 -0.51,-1.02 -0.51,6.86 -1.02,6.86 -1.02,1.27 | -1.02,-0.76 -1.02,1.27 | -1.02,1.27 -3.81,1.27 -3.81,14.73 2.29,14.73 | 2.29,14.73 2.29,5.08 -0.25,5.08 -0.25,6.6 2.03,6.6 2.03,5.33 0.25,5.33 0.25,6.35 1.52,6.35 1.52,5.84 | 1.52,5.84 0.51,5.84 | 1.52,5.84 1.78,5.84 1.78,11.43 | 1.78,13.21 1.78,14.22 -1.02,14.22 -1.02,13.97 | -1.02,13.46 -1.02,7.11 -0.51,7.11 -0.51,13.72 1.27,13.72 1.27,6.86 1.52,6.86 1.52,8.13 0,8.13 | -0.25,8.13 0,8.13 | 0,8.13 0,11.68 0.76,11.68 0.76,8.64 0.25,8.64 0.25,11.43 1.78,11.43 | 1.78,11.43 1.78,13.21 | 1.78,13.21 -1.52,13.21
  Bottom 0.61: -1.52,13.21 -1.52,13.46 | -1.52,13.46 -1.52,14.22 -3.3,14.22 -3.3,1.52 -1.52,1.52 -1.52,13.21 | -1.52,13.46 -1.02,13.46 | -1.02,13.46 -1.02,13.97 | -1.02,13.97 -2.79,13.97 -2.79,2.03 -2.03,2.03 | -1.78,2.03 -2.03,2.03 | -2.03,2.03 -2.03,13.46 -2.54,13.46 -2.54,1.78 | 2.29,14.73 3.81,14.73 13.72,22.35 32.77,22.35 33.27,22.61 33.27,19.56 33.53,19.3 36.58,19.3 | 36.58,19.3 36.83,19.3 | 36.83,19.3 38.86,19.3 38.86,17.02 38.35,17.02 38.35,18.8 | 38.35,19.05 38.35,18.8 | 38.35,18.8 33.53,18.8 | 38.86,14.48 40.13,8.38 40.13,6.1 | -2.79,23.62 -2.79,25.4 | 1.78,25.4 9.91,27.94 | 36.83,19.3 36.83,41.4 | 36.58,19.3 36.58,41.4 | 79.25,47.5 79.25,13.72 | 50.55,9.14 50.55,13.72 53.09,13.72 | 53.09,13.72 53.34,13.72 | 53.09,13.72 53.09,13.21 | 53.09,13.21 53.09,9.91 51.05,9.91 51.05,13.21 53.09,13.21 | 53.09,13.21 52.58,10.16 51.31,10.41 51.31,12.7 52.83,12.95 52.32,10.41 52.07,10.67 51.82,10.67 51.82,12.45 52.58,12.7 52.07,11.18 | 12.7,56.39 18.29,46.99
N$184
  Bottom 0.61: 72.39,18.8 74.93,18.8 74.93,24.89 72.64,24.89
N$185
  Bottom 0.61: 69.09,19.3 64.77,19.3 64.77,26.92
N$186
  Bottom 0.61: 65.28,30.48 67.31,30.48
N$187
  Bottom 0.61: 67.56,25.4 69.6,25.4
N$188
  Bottom 0.61: 55.12,27.69 56.39,27.69
N$189
  Bottom 0.61: 55.12,30.48 56.39,30.48
N$190
  Bottom 0.61: 55.12,30.23 56.39,30.23
N$191
  Bottom 0.61: 41.66,17.02 48.77,17.02 48.77,14.48 | 48.77,14.48 48.77,13.97 48.01,14.22 48.26,16.51 42.42,16.51 44.45,16.26 44.7,14.48 48.01,14.48 48.26,14.99 44.7,15.24 44.7,14.99 48.77,14.48
N$192
  Bottom 0.61: 17.53,24.38 19.56,24.38 19.56,26.42 17.27,26.67 | 14.73,28.19 17.27,28.19 17.27,26.67 | 17.27,26.67 17.27,25.65 17.78,25.4 17.78,26.67 18.8,26.67 | 17.27,26.67 18.8,24.89 19.05,24.89 19.3,25.65
N$194
  Bottom 0.61: 72.39,32.26 72.39,29.72 76.45,29.72 76.45,44.7 75.95,44.7 | 73.41,38.1 73.41,38.86 | 73.41,38.86 73.41,44.96 73.66,44.96 | 73.66,44.96 75.69,44.96 75.69,32.51 | 75.69,32.51 75.69,29.46 72.64,29.72 76.2,29.46 72.9,29.46 72.9,30.23 | 72.9,30.23 72.9,32.26 | 75.95,44.7 73.66,44.96 | 73.66,44.96 73.91,43.94 74.42,44.45 75.95,44.7 | 75.95,44.7 76.2,44.96 76.2,30.23 72.9,30.23 | 72.9,30.23 73.15,32.51 73.66,32.51 | 73.66,32.51 75.18,32.51 | 75.18,32.51 75.69,32.51 | 75.69,32.51 75.18,32.26 75.18,29.97 74.68,30.73 73.41,30.73 73.15,31.24 73.66,32.51 | 73.66,32.51 73.66,32.26 75.18,32.51 | 75.18,32.51 74.93,32 74.93,44.45 75.18,44.7 75.18,33.02 73.66,33.02 73.66,42.42 74.68,42.67 74.68,33.27 74.17,33.27 74.17,42.16 | 71.88,38.86 73.41,38.86
N$195
  Bottom 0.61: 59.69,12.19 67.31,12.19 67.31,7.87 59.69,7.87 59.69,11.94 66.8,11.94 66.8,8.13 59.94,8.38 59.94,11.68 66.29,11.68 66.29,8.38 60.45,8.38 60.2,9.4 60.2,10.92 60.45,11.18 65.79,11.18 65.79,10.16 | 65.79,9.65 65.79,8.89 60.71,8.89 60.71,10.67 65.53,10.67 65.53,9.4 60.96,9.4 61.21,10.16 65.79,10.16 | 65.79,10.16 65.79,9.65 | 65.79,9.65 61.47,9.65
N$196  (via drill 0.7 pad 1.68)
  other vias: 11.43,38.1
N$197  (via drill 0.7 pad 1.68)
  other vias: 11.43,35.56
N$198  (via drill 0.7 pad 1.68)
  other vias: 11.43,33.02
N$199  (via drill 0.7 pad 1.68)
  other vias: 13.97,38.1
N$200  (via drill 0.7 pad 1.68)
  other vias: 13.97,35.56
N$201  (via drill 0.7 pad 1.68)
  other vias: 13.97,33.02
N$202  (via drill 0.7 pad 1.68)
  other vias: 11.43,30.48
N$203  (via drill 0.7 pad 1.68)
  other vias: 13.97,30.48
N$204  (via drill 0.7 pad 1.68)
  other vias: 11.43,27.94
N$205  (via drill 0.7 pad 1.68)
  other vias: 13.97,27.94
N$206  (via drill 0.7 pad 1.68)
  other vias: 11.43,25.4
N$207  (via drill 0.7 pad 1.68)
  other vias: 13.97,25.4
N$208
  Bottom 0.61: 20.32,41.15 43.94,41.15 43.94,41.66
N$209
  Bottom 0.61: 14.99,7.37 21.34,15.24
N$210
  Bottom 0.61: 17.53,7.37 22.86,15.24
N$211
  Bottom 0.61: 20.07,7.37 24.13,15.24
N$212
  Bottom 0.61: 18.03,56.39 21.59,48.26
N$213
  Bottom 0.61: 22.86,56.13 23.88,49.02
N$214
  Bottom 0.61: 28.19,56.39 26.92,49.53
N$215
  Bottom 0.61: 38.35,56.39 32.51,49.28
N$216
  Bottom 0.61: 40.64,56.13 34.04,49.02
N$217
  Bottom 0.61: 44.2,41.4 52.32,45.47 52.07,45.72 52.07,45.47
N$218
  Bottom 0.61: 43.69,36.83 52.32,40.39
N$219
  Bottom 0.61: 43.94,35.81 52.58,38.1
N$220
  Bottom 0.61: 43.69,33.02 52.32,33.02
N$221
  Bottom 0.61: 43.94,31.75 52.58,30.48
N$222
  Bottom 0.61: 44.2,28.7 52.58,25.15
N$223
  Bottom 0.61: 43.94,26.16 52.32,20.32
N$224
  Bottom 0.61: 43.94,24.64 52.07,17.78
N$225
  Bottom 0.61: 71.63,39.12 73.15,39.12
N$226
  Bottom 0.61: 73.41,45.21 76.45,45.21 76.45,29.46

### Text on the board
Bottom: BOOT0 | RST | STM32F103 | SPSE Jecna | USR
